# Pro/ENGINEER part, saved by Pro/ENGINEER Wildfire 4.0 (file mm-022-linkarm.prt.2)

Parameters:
  METRIC = "NO"

Other parameters: PITCH, DRILL_DIAMETER, THREAD_DIAMETER, THREADS_PER_INCH, THREAD_DEPTH, THREAD_LENGTH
